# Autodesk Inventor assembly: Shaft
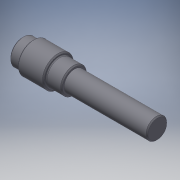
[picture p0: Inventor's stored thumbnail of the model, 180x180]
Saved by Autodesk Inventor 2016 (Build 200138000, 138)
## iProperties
Created: 2015-03
Part Number: Shaft
Document SubType Name: Assembly
Designer: Uglješa
Mass: 435.505 g
Surface Area: 107.308 cm^2
Volume: 55.4783 cm^3
Density: 7.85 g/cm^3
ClientObjectVersion: 1
Author: Uglješa
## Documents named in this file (2)
- E:\Turbokompr\Assembly1\Design Accelerator\Shaft1.iam
- E:\Turbokompr\Assembly1\Design Accelerator\Shaft1.ipt
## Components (1 placed, 1 different names)
1. Shaft:1
